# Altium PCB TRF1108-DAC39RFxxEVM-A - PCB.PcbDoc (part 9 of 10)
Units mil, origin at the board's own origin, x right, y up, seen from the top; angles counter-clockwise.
Board outline 4951.22 x 2726.56 mil, 16 copper layers (Top Layer, L2 GND1, L3 PWR1, L4 GND2, L5 PWR2, L6 GND3, L7 Ctrl Signal 1, L8 GND4, L9 GND5, L10 Ctrl Signal 2, L11 GND6, L12 PWR3, L13 GND7, L14 PWR4, L15 GND8, Bottom Layer), stack 80.2 mil thick; 705 components, 433 nets, 3633 pads, 1678 vias.
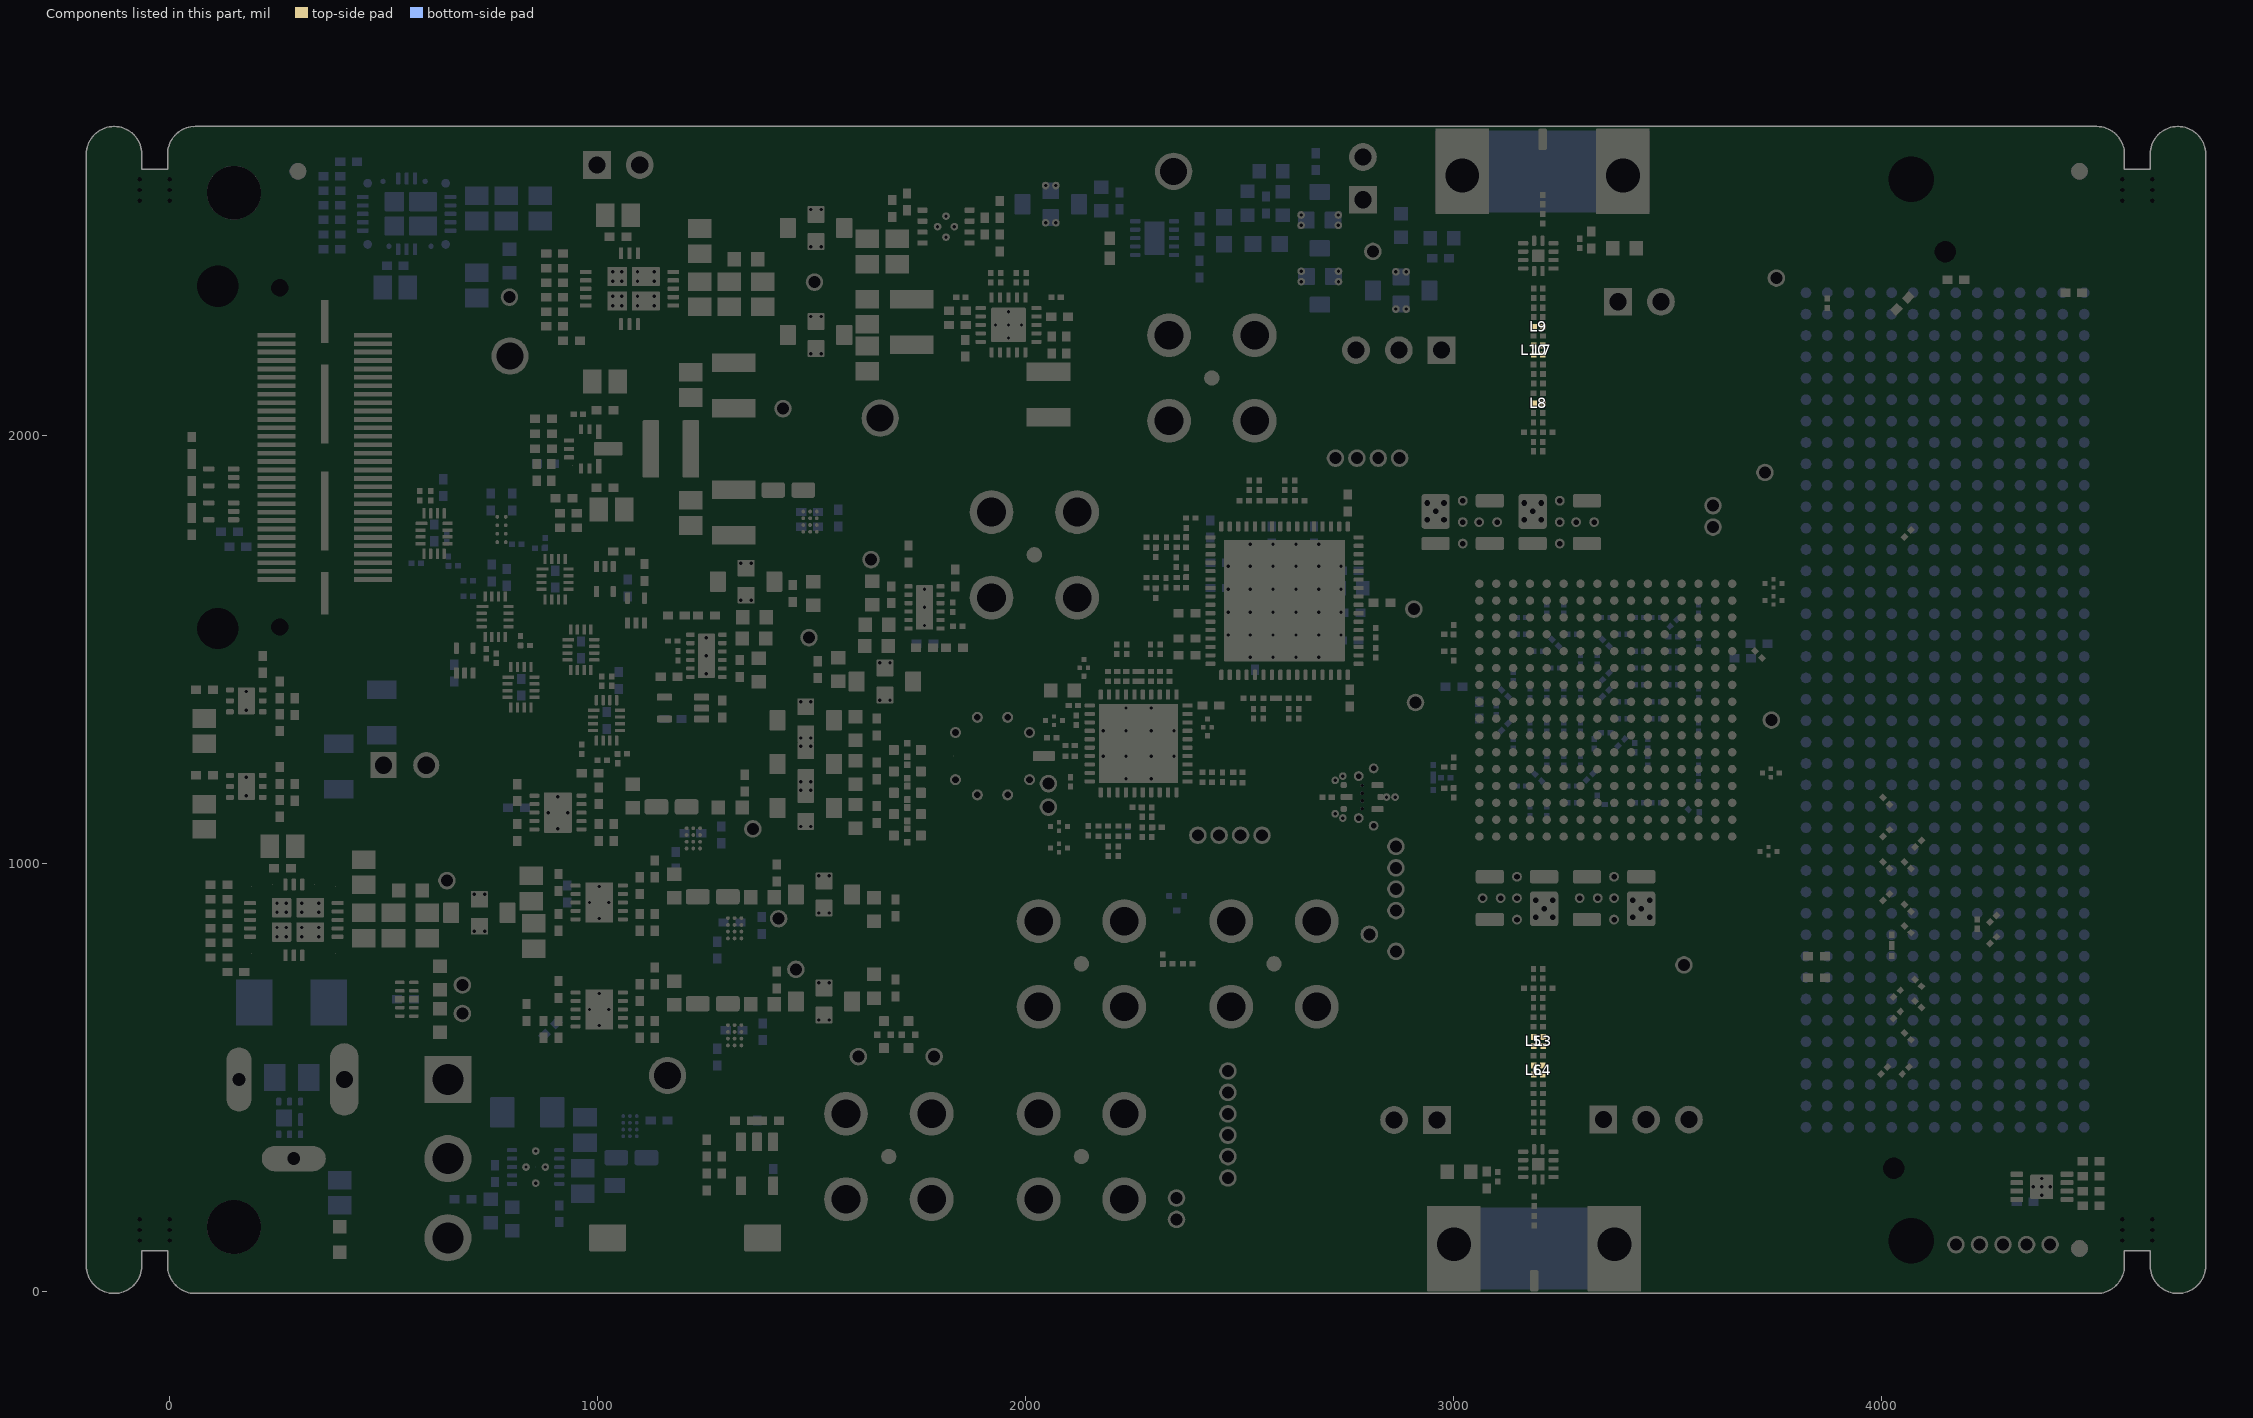
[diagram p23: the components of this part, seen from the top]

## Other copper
Top Layer:
  region net 12V: 53.27,1316.61 53.27,1359.92 140.83,1359.92 147.74,1359.92 cw(c147.74,1357.97) 149.69,1357.97 149.69,1350.06 cw(c147.74,1350.06) 147.74,1348.11 132.8,1348.11 ccw(c132.8,1338.27) 122.96,1338.27 122.96,1331.18 cw(c108.39,1331.18) 108.39,1316.61
  region net 12V: 53.27,1116.61 53.27,1159.92 140.83,1159.92 147.74,1159.92 cw(c147.74,1157.97) 149.69,1157.97 149.69,1150.06 cw(c147.74,1150.06) 147.74,1148.11 132.8,1148.11 ccw(c132.8,1138.27) 122.96,1138.27 122.96,1131.18 cw(c108.39,1131.18) 108.39,1116.61
  region net NetC108_2: 1718.11,1553.61 ccw(c1718.11,1551.64) 1716.14,1551.64 1716.14,1545.73 cw(c1695,1545.73) 1695,1524.59 1663.35,1524.59 1663.35,1491.13 1694.84,1491.13 cw(c1694.84,1467.86) 1718.11,1467.86 1718.11,1402.99 ccw(c1719.98,1402.99) 1719.98,1401.12 1753.64,1401.12 ccw(c1753.64,1402.99) 1755.51,1402.99 1755.51,1446.49 1755.51,1516.55 ccw(c1747,1516.55) 1747,1525.06 cw(c1747,1536.23) 1735.83,1536.23 1735.83,1551.64 ccw(c1733.86,1551.64) 1733.86,1553.61
  region net 3p8V_Clock_LDO: 1712.5,1612.66 cw(c1712.5,1616.01) 1709.15,1616.01 ccw(c1705.61,1616.01) 1705.61,1619.55 1676.14,1619.55 1624.25,1619.55 1624.25,1588.05 1665.14,1588.05 ccw(c1665.14,1591.01) 1668.1,1591.01 cw(c1673.02,1591.01) 1673.02,1595.93 1706.12,1595.93 ccw(c1706.12,1597.9) 1708.08,1597.9 cw(c1713.01,1597.9) 1713.01,1602.82 1733.86,1602.82 ccw(c1733.86,1604.79) 1735.83,1604.79 1735.83,1610.69 ccw(c1733.86,1610.69) 1733.86,1612.66
  region net VEExB: 1497.13,1440.49 ccw(c1493.16,1440.49) 1493.16,1444.46 1445.89,1444.46 ccw(c1445.89,1434.46) 1435.89,1434.46 1435.89,1414.46 ccw(c1445.89,1414.46) 1445.89,1404.46 1492.61,1404.46 ccw(c1492.61,1408.99) 1497.13,1408.99 1580.6,1408.99 cw(c1580.6,1403.37) 1586.22,1403.37 1586.22,1402.99 1588.09,1401.12 1621.75,1401.12 1623.62,1402.99 1623.62,1446.49 ccw(c1621.75,1446.49) 1621.75,1448.36 1588.09,1448.36 ccw(c1588.09,1446.49) 1586.22,1446.49 1586.22,1446.11 cw(c1580.6,1446.11) 1580.6,1440.49
  region net NetR90_1: 1792.91,1553.61 ccw(c1792.91,1551.64) 1790.94,1551.64 1790.94,1537.21 cw(c1780.31,1537.21) 1780.31,1526.57 ccw(c1780.31,1517.52) 1771.26,1517.52 1771.26,1493.84 1824.88,1493.84 1824.88,1515.33 ccw(c1817.64,1515.33) 1817.64,1522.57 cw(c1817.64,1529.58) 1810.63,1529.58 1810.63,1551.64 ccw(c1808.66,1551.64) 1808.66,1553.61
  region net 3p8V_Clock_LDO: 1624.25,1619.55 ccw(c1620.28,1619.55) 1620.28,1623.53 1573.01,1623.53 ccw(c1573.01,1613.53) 1563.01,1613.53 1563.01,1593.53 ccw(c1573.01,1593.53) 1573.01,1583.53 1619.72,1583.53 ccw(c1619.72,1588.05) 1624.25,1588.05 1657.72,1588.05 1657.72,1619.55
  region net VDDCSR: 1666.8,1112.95 ccw(c1667.07,1118.15) 1667.07,1112.94 cw(c1667.07,1104.67) 1675.34,1104.67 1675.34,1055.31 ccw(c1677.74,1055.31) 1677.74,1052.91 1701.32,1052.91 ccw(c1701.32,1055.28) 1703.68,1055.28 1703.68,1174.17 ccw(c1701.32,1174.17) 1701.32,1176.53 1682.42,1176.53 ccw(c1682.42,1174.17) 1680.06,1174.17 1680.06,1171.3 cw(c1661.87,1171.3) 1661.87,1153.11 1661.87,1133.43 1652.02,1133.43 1642.18,1121.61 1645.27,1121.61 cw(c1645.27,1117.13) 1649.75,1117.13 ccw(c1653.94,1117.13) 1653.94,1112.94 1666.55,1112.94 ccw(c1666.55,1117.56)
  region net VDDCSR: 1661.87,1121.61 1661.87,1153.11 1535.19,1153.11 ccw(c1535.19,1151.24) 1533.32,1151.24 1533.32,1107.74 ccw(c1535.19,1107.74) 1535.19,1105.87 1568.85,1105.87 ccw(c1568.85,1107.74) 1570.72,1107.74 cw(c1584.6,1107.74) 1584.6,1121.61
  region net VDDCLK18: 1743.05,1055.28 1743.05,1074.18 cw(c1745.41,1074.18) 1745.41,1076.54 1764.31,1076.54 cw(c1772.38,1076.54) 1772.38,1084.61 1794.86,1084.61 cw(c1794.86,1074.53) 1804.94,1074.53 1804.94,1054.79 cw(c1794.71,1054.79) 1794.71,1044.56 1772.67,1044.56 cw(c1772.67,1052.92) 1764.31,1052.92 1745.41,1052.92 cw(c1745.41,1055.28)
  region net VDDSYS18: 1743.05,1105.28 1743.05,1124.18 cw(c1745.41,1124.18) 1745.41,1126.54 1764.31,1126.54 cw(c1772.38,1126.54) 1772.38,1134.61 1794.86,1134.61 cw(c1794.86,1124.53) 1804.94,1124.53 1804.94,1104.79 cw(c1794.71,1104.79) 1794.71,1094.56 1772.67,1094.56 cw(c1772.67,1102.92) 1764.31,1102.92 1745.41,1102.92 cw(c1745.41,1105.28)
  region net VDDR: 1743.05,1155.28 1743.05,1174.18 cw(c1745.41,1174.18) 1745.41,1176.54 1764.31,1176.54 cw(c1772.38,1176.54) 1772.38,1184.61 1794.86,1184.61 cw(c1794.86,1174.53) 1804.94,1174.53 1804.94,1154.79 cw(c1794.71,1154.79) 1794.71,1144.56 1772.67,1144.56 cw(c1772.67,1152.92) 1764.31,1152.92 1745.41,1152.92 cw(c1745.41,1155.28)
  region net VDDIO: 1668.76,1326.34 ccw(c1672.73,1326.34) 1672.73,1322.36 1720,1322.36 ccw(c1720,1332.36) 1730,1332.36 1730,1352.36 ccw(c1720,1352.36) 1720,1362.36 1673.28,1362.36 ccw(c1673.28,1357.83) 1668.76,1357.83 1535.19,1357.83 ccw(c1535.19,1355.96) 1533.32,1355.96 1533.32,1312.46 ccw(c1535.19,1312.46) 1535.19,1310.59 1568.85,1310.59 ccw(c1568.85,1312.46) 1570.72,1312.46 cw(c1584.6,1312.46) 1584.6,1326.34
  region net VDDA18A: 1743.05,1205.28 1743.05,1224.18 cw(c1745.41,1224.18) 1745.41,1226.54 1764.31,1226.54 cw(c1772.38,1226.54) 1772.38,1234.61 1794.86,1234.61 cw(c1794.86,1224.53) 1804.94,1224.53 1804.94,1204.79 cw(c1794.71,1204.79) 1794.71,1194.56 1772.67,1194.56 cw(c1772.67,1202.92) 1764.31,1202.92 1745.41,1202.92 cw(c1745.41,1205.28)
  region net VDDA18B: 1743.05,1255.28 1743.05,1274.18 cw(c1745.41,1274.18) 1745.41,1276.54 1764.31,1276.54 cw(c1772.38,1276.54) 1772.38,1284.61 1794.86,1284.61 cw(c1794.86,1274.53) 1804.94,1274.53 1804.94,1254.79 cw(c1794.71,1254.79) 1794.71,1244.56 1772.67,1244.56 cw(c1772.67,1252.92) 1764.31,1252.92 1745.41,1252.92 cw(c1745.41,1255.28)
  region net VDDLA: 1716.61,579.99 1735.5,579.99 cw(c1735.5,577.63) 1737.87,577.63 1737.87,558.74 cw(c1737.87,550.67) 1745.93,550.67 1745.93,528.18 cw(c1735.86,528.18) 1735.86,518.11 1716.11,518.11 cw(c1716.11,528.33) 1705.89,528.33 1705.89,550.38 cw(c1714.24,550.38) 1714.24,558.74 1714.24,577.63 cw(c1716.61,577.63)
  region net VDDLB: 1659.41,579.99 1678.31,579.99 cw(c1678.31,577.63) 1680.67,577.63 1680.67,558.73 cw(c1680.67,550.67) 1688.74,550.67 1688.74,528.18 cw(c1678.66,528.18) 1678.66,518.11 1658.92,518.11 cw(c1658.92,528.33) 1648.69,528.33 1648.69,550.38 cw(c1657.05,550.38) 1657.05,558.73 1657.05,577.63 cw(c1659.41,577.63)
  region net VDDL: 1575.89,699.11 cw(c1577.76,699.11) 1577.76,700.98 1734.32,700.98 cw(c1734.32,697.29) 1738.01,697.29 1738.01,627.8 cw(c1729.28,627.8) 1729.28,619.37 1707,619.37 1707,619.4 cw(c1706.4,625.34) 1706.4,619.37 1662.84,619.37 cw(c1662.84,625.34) 1656.87,625.34 1656.87,637.48 ccw(c1640.61,637.48) 1640.61,653.74 1577.76,653.74 cw(c1577.76,655.61) 1575.89,655.61
  region net VDDA: 1661.87,1223.98 cw(c1661.87,1205.79) 1680.06,1205.79 1680.06,1205.28 ccw(c1682.42,1205.28) 1682.42,1202.91 1701.32,1202.91 ccw(c1701.32,1205.28) 1703.68,1205.28 1703.68,1274.17 ccw(c1701.32,1274.17) 1701.32,1276.53 1682.42,1276.53 ccw(c1682.42,1274.17) 1680.06,1274.17 1680.06,1273.66 cw(c1661.87,1273.66) 1661.87,1255.47 1535.19,1255.47 ccw(c1535.19,1253.6) 1533.32,1253.6 1533.32,1210.1 ccw(c1535.19,1210.1) 1535.19,1208.23 1568.85,1208.23 ccw(c1568.85,1210.1) 1570.72,1210.1 cw(c1584.6,1210.1) 1584.6,1223.98 1661.87,1223.98
  region net VDDCLK10: 1575.89,905.61 ccw(c1577.76,905.61) 1577.76,903.74 1734.32,903.74 ccw(c1734.32,907.43) 1738.01,907.43 1738.01,976.93 ccw(c1729.28,976.93) 1729.28,985.35 1707,985.35 1707,985.32 ccw(c1706.4,979.38) 1706.4,985.35 1662.84,985.35 ccw(c1662.84,979.38) 1656.87,979.38 1656.87,967.24 cw(c1640.61,967.24) 1640.61,950.98 1577.76,950.98 ccw(c1577.76,949.11) 1575.89,949.11
  region net NetFB4_1: 1282.3,653.74 cw(c1282.3,659.72) 1276.32,659.72 1276.32,683.98 cw(c1282.3,683.98) 1282.3,689.96 1370.57,689.96 cw(c1370.57,687.2) 1373.33,687.2 1373.33,653.74 1282.3,653.74
  region net NetFB5_1: 1282.3,903.74 cw(c1282.3,909.72) 1276.32,909.72 1276.32,933.98 cw(c1282.3,933.98) 1282.3,939.96 1370.57,939.96 cw(c1370.57,937.2) 1373.33,937.2 1373.33,903.74 1282.3,903.74
  region net NetFB3_1: 1185.8,1113.74 cw(c1185.8,1119.72) 1179.82,1119.72 1179.82,1143.98 cw(c1185.8,1143.98) 1185.8,1149.96 1229.36,1149.96 ccw(c1232.11,1149.96) 1232.11,1147.2 1297.85,1147.2 1297.85,1113.74
  region net NetC52_2: 1391.98,1105.87 1436.96,1105.87 ccw(c1436.96,1107.74) 1438.83,1107.74 1438.83,1355.96 ccw(c1436.96,1355.96) 1436.96,1357.83 1403.3,1357.83 ccw(c1403.3,1355.96) 1401.43,1355.96 1401.43,1197.49 cw(c1384.04,1197.49) 1384.04,1180.09 1373.82,1180.09 ccw(c1373.82,1161.87) 1364.1,1177.28 1352.97,1177.28 1333.29,1177.28 1333.29,1165.23 cw(c1326.95,1165.23) 1326.95,1158.9 ccw(c1326.95,1153.42) 1321.48,1153.42 1321.48,1147.6 1321.48,1111.38 1321.48,1065.09 ccw(c1328.61,1065.09) 1328.61,1057.96 1381.66,1057.96 ccw(c1381.66,1068.17) 1391.87,1068.17 1391.87,1104.64 cw(c1398.61,1104.64)
  region net GND: 946.2,1932.16 946.2,1911.1 944.43,1911.1 925.99,1892.66 ccw(c956.38,1862.27) 913.4,1862.27 913.4,1842.58 846.89,1842.58 cw(c846.89,1879.2) 821,1853.31 cw(c853.73,1886.04) 807.44,1886.04 807.44,2003.43 cw(c860.57,2005.25) 821.71,2041.54 cw(c839.56,2020.63) 841.72,2048.03 865.35,2048.03 865.35,1993.35 841.72,1993.35 ccw(c841.72,1982.89) 831.27,1982.89 831.27,1884.86 ccw(c841.11,1884.86) 841.11,1875.02 875.08,1875.02 ccw(c875.08,1882.01) 882.06,1882.01 882.06,1905.63 901.75,1905.63 916.86,1920.75 ccw(c905.45,1932.16) 921.59,1932.16 923.17,1933.74 944.62,1933.74
  pour cut-out: 2554,765 ccw(c2580,765) 2580,739 ccw(c2580,765) 2606,765 ccw(c2580,765) 2580,791 ccw(c2580,765)
  pour cut-out: 2104,765 ccw(c2130,765) 2130,739 ccw(c2130,765) 2156,765 ccw(c2130,765) 2130,791 ccw(c2130,765)
  pour cut-out: 1654,315 ccw(c1680,315) 1680,289 ccw(c1680,315) 1706,315 ccw(c1680,315) 1680,341 ccw(c1680,315)
  pour cut-out: 2104,315 ccw(c2130,315) 2130,289 ccw(c2130,315) 2156,315 ccw(c2130,315) 2130,341 ccw(c2130,315)
  pour cut-out: 1994,1720.62 ccw(c2020,1720.62) 2020,1694.62 ccw(c2020,1720.62) 2046,1720.62 ccw(c2020,1720.62) 2020,1746.62 ccw(c2020,1720.62)
  pour cut-out: 2408.73,2133.69 ccw(c2434.73,2133.69) 2434.73,2107.69 ccw(c2434.73,2133.69) 2460.73,2133.69 ccw(c2434.73,2133.69) 2434.73,2159.69 ccw(c2434.73,2133.69)
  region net NetC147_2: 2149.41,1363.65 2159.26,1363.65 ccw(c2159.26,1365.62) 2161.22,1365.62 2161.22,1371.53 ccw(c2159.26,1371.53) 2159.26,1373.5 2149.41,1373.5 cw(c2149.41,1383.34) 2139.57,1383.34 2139.57,1410.47 ccw(c2129.5,1410.47) 2129.5,1420.54 2098,1420.54 2098,1387.07 2103.13,1387.07 cw(c2103.13,1374.87) 2115.33,1374.87 2115.33,1362.28 2157.88,1362.28 ccw(c2157.88,1365.62) 2161.22,1365.62
  region net NetC44_2: 574.14,862.75 ccw(c576.11,862.75) 576.11,860.79 674.53,860.79 ccw(c674.53,862.66) 676.4,862.66 676.4,978.53 ccw(c669.58,978.53) 669.58,985.35 584.08,985.35 ccw(c584.08,975.42) 574.14,975.42 574.14,884.41
  region net NetC125_2: 1479.53,903.74 ccw(c1479.53,905.61) 1481.4,905.61 1481.4,949.11 ccw(c1479.53,949.11) 1479.53,950.98 1468.96,950.98 cw(c1468.96,959.6) 1460.34,959.6 ccw(c1452.66,959.6) 1452.66,967.28 1408.76,967.28 1408.76,955.23 cw(c1402.43,955.23) 1402.43,948.9 ccw(c1402.43,943.42) 1396.95,943.42 1396.95,847.92 ccw(c1402.63,847.92) 1402.63,842.25 1444.78,842.25 ccw(c1444.78,849.47) 1451.99,849.47 1451.99,893.03 cw(c1462.7,893.03) 1462.7,903.74
  region net 3p8V_Clock_LDO: 1393.1,1463.07 ccw(c1397.07,1463.07) 1397.07,1459.09 1444.34,1459.09 ccw(c1444.34,1469.09) 1454.34,1469.09 1454.34,1489.09 ccw(c1444.34,1489.09) 1444.34,1499.09 1397.63,1499.09 ccw(c1397.63,1494.57) 1393.1,1494.57 1359.63,1494.57 1359.63,1463.07
  region net 1p0V_DAC: 1456.3,2033.12 ccw(c1456.3,2039.28) 1462.46,2039.28 1462.46,2075.95 ccw(c1453.57,2075.95) 1453.57,2084.84 1368.93,2084.84 1266.57,2084.84 cw(c1266.57,2093.84) 1257.57,2093.84 1257.57,2099.48 ccw(c1247.21,2099.48) 1247.2,2109.84 1190.19,2109.84 1190.19,1826.54 1245.31,1826.54 ccw(c1245.31,1837) 1255.78,1837 1255.78,1840.74 cw(c1266.57,1840.74) 1266.57,1851.54 1429.5,1851.54 ccw(c1429.5,1859.67) 1437.64,1859.67 1437.64,1883.94 ccw(c1426.74,1883.94) 1426.73,1894.84 1386.33,1894.84 cw(c1393.08,1919) 1368.93,1912.24 1368.93,1987.87 1368.93,2017.23 cw(c1384.84,2017.2) 1384.84,2033.12
  region net 3p8V_Clock_LDO: 1460.88,2210.43 ccw(c1460.88,2212.3) 1462.75,2212.3 1462.75,2255.81 1462.75,2295.92 cw(c1495.44,2295.92) 1495.44,2328.61 1528.13,2328.61 ccw(c1528.13,2337.33) 1536.85,2337.33 1536.85,2369.85 ccw(c1525.99,2369.85) 1525.99,2380.71 1481.35,2380.71 cw(c1481.35,2399.31) 1462.75,2399.31 1462.75,2505.81 ccw(c1460.88,2505.81) 1460.88,2507.68 1427.22,2507.68 ccw(c1427.22,2505.81) 1425.35,2505.81 1425.35,2462.3 cw(c1390.91,2462.3) 1390.91,2427.87 1358.38,2427.87 1358.38,2337.4 1399.18,2337.4 cw(c1399.18,2311.24) 1425.35,2311.24 1425.35,2212.3 ccw(c1427.22,2212.3) 1427.22,2210.43
  region net PwrGd_Analog: 122.96,940.14 169.25,940.14 cw(c169.25,935.59) 173.8,935.59 173.8,929.68 ccw(c175.77,929.68) 175.77,927.72 208.25,927.72 ccw(c208.25,929.69) 210.22,929.69 210.22,962.17 ccw(c208.45,962.17) 208.45,963.94 202.35,963.94 202.35,964.13 127.27,964.13 ccw(c127.27,959.83) 122.96,959.83
  region net NetC41_2: 378.53,864.65 cw(c369.48,864.53) 378.53,864.62 ccw(c380.49,864.72) 380.49,862.75 550.52,862.75 550.52,953.22 512.35,953.22 cw(c512.35,964.35) 501.22,964.35 ccw(c494.55,964.35) 494.55,971.02 313.57,971.02 ccw(c313.57,962.16) 304.71,962.16 304.71,938.54 304.71,925.68 cw(c297.89,925.68) 297.89,918.86 ccw(c297.89,916.82) 295.85,916.82 295.85,875.62 ccw(c297.89,875.62) 297.89,873.58 369.48,873.58 cw(c369.48,864.53) 378.53,864.72 ccw(c380.49,864.72)
  region net NetC17_2: 1162.77,2339.3 cw(c1153.71,2339.17) 1162.77,2339.27 ccw(c1164.73,2339.37) 1164.73,2337.4 1334.76,2337.4 1334.76,2427.87 1296.59,2427.87 cw(c1296.59,2439) 1285.46,2439 ccw(c1278.79,2439) 1278.79,2445.67 1097.81,2445.67 ccw(c1097.81,2436.81) 1088.95,2436.81 1088.95,2413.19 1088.95,2400.32 cw(c1082.13,2400.32) 1082.13,2393.5 ccw(c1082.13,2391.47) 1080.09,2391.47 1080.09,2350.27 ccw(c1082.13,2350.27) 1082.13,2348.23 1153.71,2348.23 cw(c1153.71,2339.17) 1162.77,2339.37 ccw(c1164.73,2339.37)
  region net PwrGd_Clock: 907.2,2414.79 953.49,2414.79 cw(c953.49,2410.24) 958.04,2410.24 958.04,2404.33 ccw(c960.01,2404.33) 960.01,2402.36 992.49,2402.36 ccw(c992.49,2404.33) 994.46,2404.33 994.46,2436.81 ccw(c992.69,2436.81) 992.69,2438.58 986.59,2438.58 986.59,2438.78 911.51,2438.78 ccw(c911.51,2434.47) 907.2,2434.47
  region net GND: 1051.55,2411.22 cw(c1051.55,2413.19) 1049.58,2413.19 1049.58,2436.81 cw(c1051.55,2436.81) 1051.55,2438.78 ccw(c1051.55,2442.72) 1055.48,2442.72 1055.48,2541.88 1098.79,2541.88 1098.79,2486.76 cw(c1090.67,2486.76) 1090.67,2478.65 1084.59,2478.65 ccw(c1084.59,2473.17) 1079.11,2473.17 1079.11,2413.19 cw(c1077.14,2413.19) 1077.14,2411.22
  region net GND: 267.31,936.57 cw(c267.31,938.54) 265.34,938.54 265.34,962.16 cw(c267.31,962.16) 267.31,964.13 ccw(c267.31,968.07) 271.24,968.07 271.24,1067.24 314.55,1067.24 314.55,1012.12 cw(c306.43,1012.12) 306.43,1004 300.35,1004 ccw(c300.35,998.52) 294.87,998.52 294.87,938.54 cw(c292.9,938.54) 292.9,936.57
  region net GND: 162.33,736.14 267.52,736.14 ccw(c267.52,743.27) 274.64,743.27 275.19,796.81 cw(c285.6,796.81) 285.6,807.23 295.89,807.23 cw(c295.09,797.61) 304.71,796.81 304.71,743.27 ccw(c311.5,742.93) 311.17,736.14 414.43,736.35 ccw(c414.43,745.98) 424.06,745.98 424.06,801.67 cw(c426.09,801.67) 426.09,803.7 629.26,803.7 629.26,847.01 422.04,847.01 cw(c422.04,850.94) 418.1,850.94 ccw(c416.14,850.95) 416.13,852.91 373.2,852.91 cw(c373.2,856.35) 369.76,856.35 ccw(c364.34,856.35) 364.34,861.77 296.45,861.77 cw(c296.89,874.66) 284.04,873.58 284.04,916.82 ccw(c282,916.82) 282,918.86 182.66,918.86 ccw(c182.66,910) 173.8,910 173.8,904.09 ccw(c175.77,904.09) 175.77,902.12 200.1,902.12 cw(c200.11,889.1) 213.14,889.09 213.26,889.09 213.26,812.65 cw(c208.26,812.64) 208.25,807.64 191.63,807.64 ccw(c191.62,778.34) 162.33,778.34
  region net GND: 1143.45,580.51 1058.54,580.51 cw(c1058.54,592.25) 1046.8,592.25 1046.8,621.46 cw(c1049.16,621.46) 1049.16,623.82 1068.06,623.82 cw(c1068.06,621.46) 1070.42,621.46 1070.42,616.73 ccw(c1083.02,616.73) 1083.02,604.13 1143.45,604.13
  region net GND: 1143.45,830.51 1058.54,830.51 cw(c1058.54,842.25) 1046.8,842.25 1046.8,871.46 cw(c1049.16,871.46) 1049.16,873.82 1068.06,873.82 cw(c1068.06,871.46) 1070.42,871.46 1070.42,866.73 ccw(c1083.02,866.73) 1083.02,854.13 1143.45,854.13
  region net GND: 1053.48,1944.57 ccw(c1020.6,1942.99) 1019.03,1942.99 1019.03,1912.88 ccw(c1020.8,1912.88) 1020.8,1911.1 cw(c1020.8,1906.97) 1024.93,1906.97 1024.93,1866.81 ccw(c1031.74,1866.81) 1031.74,1860 1033.88,1860 cw(c1033.88,1854.09) 1039.78,1854.09 1039.78,1798.98 1083.09,1798.98 1083.09,1863.79 ccw(c1063.27,1863.79) 1063.27,1883.61 cw(c1063.27,1891.44) 1055.45,1891.44 1055.45,1942.6 ccw(c1053.48,1942.6)
  region net GND: 1053.48,1991.81 ccw(c1053.48,1993.78) 1054.87,1992.39 ccw(c1053.48,1993.78) 1055.45,1993.78 1055.45,2067.14 cw(c1099.13,2067.14) 1068.24,2098.03 1068.24,2153.15 1024.93,2153.15 1024.93,2048.7 1024.93,2035.25 cw(c1010.82,2035.25) 1020.8,2025.28 ccw(c1020.8,2023.5) 1019.03,2023.5 1019.03,1993.39 ccw(c1020.6,1993.39) 1020.6,1991.81
  region net NetC11_2: 1757.32,2187.4 cw(c1749.82,2178.57) 1761.41,2178.57 ccw(c1768.17,2178.57) 1768.17,2171.81 1933.21,2171.81 ccw(c1933.21,2183.31) 1944.71,2183.31 1944.71,2204.09 ccw(c1943.29,2204.09) 1943.29,2205.51 1916.01,2205.51 cw(c1916.01,2215) 1906.52,2215 1906.52,2221.61 ccw(c1905.1,2221.61) 1905.1,2223.03 1884.32,2223.03 ccw(c1884.32,2221.61) 1882.9,2221.61 1882.9,2209.58 cw(c1868.75,2209.58) 1868.75,2195.43 1833.31,2195.43 cw(c1833.31,2206.87) 1821.88,2206.87 ccw(c1795.28,2206.87) 1821.78,2209.08 1821.88,2209 ccw(c1796.5,2209) 1814.44,2226.95 1798.91,2242.48 ccw(c1788.76,2232.44) 1798.8,2242.6 ccw(c1764.27,2207.95) 1764.27,2256.86 1762.86,2256.86 1762.92,2256.81 ccw(c1761.41,2233.46) 1761.41,2256.86 1678.65,2256.86 cw(c1678.65,2278.07) 1657.44,2278.07 1657.44,2280.71 1582.14,2280.71 ccw(c1582.14,2255.81) 1557.24,2255.81 1557.24,2212.3 ccw(c1582.14,2212.3) 1582.14,2187.4
  region net GND: 1046.95,1040.51 962.04,1040.51 cw(c962.04,1052.25) 950.3,1052.25 950.3,1081.46 cw(c952.66,1081.46) 952.66,1083.82 971.56,1083.82 cw(c971.56,1081.46) 973.92,1081.46 973.92,1076.73 ccw(c986.52,1076.73) 986.52,1064.13 1046.95,1064.13
  region net NetR85_1: 1224.44,1529.01 ccw(c1224.44,1530.98) 1226.41,1530.98 1226.41,1545.41 cw(c1237.04,1545.41) 1237.04,1556.05 ccw(c1237.04,1565.1) 1246.09,1565.1 1246.09,1588.78 1192.47,1588.78 1192.47,1567.3 ccw(c1199.71,1567.3) 1199.71,1560.05 cw(c1199.71,1553.04) 1206.72,1553.04 1206.72,1530.98 ccw(c1208.69,1530.98) 1208.69,1529.01
  region net NetC100_2: 1299.24,1529.01 ccw(c1299.24,1530.98) 1301.21,1530.98 1301.21,1536.89 cw(c1322.35,1536.89) 1322.35,1558.03 1354,1558.03 1354,1591.49 1322.51,1591.49 cw(c1322.51,1614.76) 1299.24,1614.76 1299.24,1679.63 ccw(c1297.37,1679.63) 1297.37,1681.5 1263.71,1681.5 ccw(c1263.71,1679.63) 1261.84,1679.63 1261.84,1636.13 1261.84,1566.07 ccw(c1270.35,1566.07) 1270.35,1557.56 cw(c1270.35,1546.39) 1281.52,1546.39 1281.52,1530.98 ccw(c1283.49,1530.98) 1283.49,1529.01
  region net 3p8V_Clock_LDO: 1304.85,1469.96 cw(c1304.85,1466.61) 1308.2,1466.61 ccw(c1311.74,1466.61) 1311.74,1463.07 1341.21,1463.07 1393.1,1463.07 1393.1,1494.57 1352.21,1494.57 ccw(c1352.21,1491.61) 1349.25,1491.61 cw(c1344.33,1491.61) 1344.33,1486.69 1311.23,1486.69 ccw(c1311.23,1484.72) 1309.27,1484.72 cw(c1304.34,1484.72) 1304.34,1479.8 1283.49,1479.8 ccw(c1283.49,1477.83) 1281.52,1477.83 1281.52,1471.93 ccw(c1283.49,1471.93) 1283.49,1469.96
  region net VEExA: 1520.22,1642.13 ccw(c1524.19,1642.13) 1524.19,1638.16 1571.46,1638.16 ccw(c1571.46,1648.16) 1581.46,1648.16 1581.46,1668.16 ccw(c1571.46,1668.16) 1571.46,1678.16 1524.74,1678.16 ccw(c1524.74,1673.63) 1520.22,1673.63 1436.75,1673.63 cw(c1436.75,1679.25) 1431.13,1679.25 1431.13,1679.63 1429.26,1681.5 1395.6,1681.5 1393.73,1679.63 1393.73,1636.13 ccw(c1395.6,1636.13) 1395.6,1634.26 1429.26,1634.26 ccw(c1429.26,1636.13) 1431.13,1636.13 1431.13,1636.51 cw(c1436.75,1636.51) 1436.75,1642.13
  region net GND: 1784.8,2339.76 1784.8,2284.94 cw(c1773.99,2284.94) 1773.99,2274.12 1693.62,2274.12 cw(c1693.62,2285.3) 1682.44,2285.3 1682.44,2339.76
  region net GND: 1266.57,1745.24 1266.57,1800.06 cw(c1277.38,1800.06) 1277.38,1810.88 1357.75,1810.88 cw(c1357.75,1799.7) 1368.93,1799.7 1368.93,1745.24
  region net GND: 1368.93,2191.14 1368.93,2136.32 cw(c1358.11,2136.32) 1358.11,2125.5 1277.75,2125.5 cw(c1277.75,2136.68) 1266.57,2136.68 1266.57,2191.14
  region net NetC51_2: 980.94,1113.74 1065.37,1113.74 1147.85,1113.74 1147.85,1147.2 ccw(c1145.1,1147.2) 1145.1,1149.96 992.26,1149.96 cw(c992.26,1156.62) 985.61,1156.62 985.61,1159.59 ccw(c982.64,1159.59) 982.64,1162.56 952.66,1162.56 ccw(c952.66,1160.2) 950.3,1160.2 950.3,1116.1 ccw(c952.66,1116.1) 952.66,1113.74 980.88,1113.74 ccw(c980.88,1118.46)
  region net NetC124_2: 1077.44,903.74 1161.87,903.74 1244.35,903.74 1244.35,937.2 ccw(c1241.6,937.2) 1241.6,939.96 1088.76,939.96 cw(c1088.76,946.62) 1082.11,946.62 1082.11,949.59 ccw(c1079.14,949.59) 1079.14,952.56 1049.16,952.56 ccw(c1049.16,950.2) 1046.8,950.2 1046.8,906.1 ccw(c1049.16,906.1) 1049.16,903.74 1077.38,903.74 ccw(c1077.38,908.46)
  region net NetC116_2: 1077.44,653.74 1161.87,653.74 1244.35,653.74 1244.35,687.2 ccw(c1241.6,687.2) 1241.6,689.96 1088.76,689.96 cw(c1088.76,696.62) 1082.11,696.62 1082.11,699.59 ccw(c1079.14,699.59) 1079.14,702.56 1049.16,702.56 ccw(c1049.16,700.2) 1046.8,700.2 1046.8,656.1 ccw(c1049.16,656.1) 1049.16,653.74 1077.38,653.74 ccw(c1077.38,658.46)
  region net NetC24_2: 1762.84,2437.4 ccw(c1762.84,2444.87) 1770.3,2444.87 1770.3,2478.76 ccw(c1768.35,2478.76) 1768.35,2480.71 1638.28,2480.71 ccw(c1638.25,2477.95) 1638.25,2480.71 1627.05,2480.71 cw(c1627.05,2489.01) 1618.75,2489.01 1618.75,2480.71 1618.75,2497.31 ccw(c1608.39,2497.31) 1608.39,2507.68 1558.05,2507.68 ccw(c1558.05,2505.81) 1556.18,2505.81 1556.18,2462.3 ccw(c1558.05,2462.3) 1558.05,2460.43 1564.11,2460.43 cw(c1564.11,2451.1) 1573.45,2451.1 ccw(c1587.14,2451.1) 1587.14,2437.4
  region net GND: 2002.11,2020.04 2002.11,2074.87 cw(c2012.93,2074.87) 2012.93,2085.69 2093.29,2085.69 cw(c2093.29,2074.51) 2104.47,2074.51 2104.47,2020.04
  region net 3p3V_Utility: 329.54,1334.33 ccw(c329.54,1346.49) 341.7,1346.49 ccw(c330.23,1346.49) 330.23,1357.95 269.41,1357.95 cw(c269.41,1359.92) 267.45,1359.92 217.6,1359.92 210.69,1359.92 ccw(c210.69,1357.97) 208.74,1357.97 208.74,1350.06 ccw(c210.69,1350.06) 210.69,1348.11 229.94,1348.11 cw(c229.94,1342.81) 235.24,1342.81 ccw(c241.75,1342.81) 241.75,1336.3 280.79,1336.3 cw(c280.79,1334.33) 282.76,1334.33 302.45,1334.33
  region net 5V_Utility: 329.54,1134.33 ccw(c329.54,1146.49) 341.7,1146.49 ccw(c330.23,1146.49) 330.23,1157.95 269.41,1157.95 cw(c269.41,1159.92) 267.45,1159.92 217.6,1159.92 210.69,1159.92 ccw(c210.69,1157.97) 208.74,1157.97 208.74,1150.06 ccw(c210.69,1150.06) 210.69,1148.11 229.94,1148.11 cw(c229.94,1142.81) 235.24,1142.81 ccw(c241.75,1142.81) 241.75,1136.3 280.79,1136.3 cw(c280.79,1134.33) 282.76,1134.33 302.45,1134.33
  region net 3p3V_Clock: 1856.92,2442.91 1856.92,2480.71 1948.57,2480.71 1950.71,2480.71 ccw(c1950.71,2489) 1959,2489 cw(c1968,2489) 1968,2498 1989,2498 cw(c1989,2489) 1998,2489 1998,2448 cw(c1989,2448) 1989,2439 1968,2439 cw(c1968,2448) 1959,2448 ccw(c1949.91,2448) 1949.91,2457.09 1903.88,2457.09 ccw(c1903.88,2452.2) 1899,2452.2 1899,2452 cw(c1889.91,2452) 1889.91,2442.91 1888.59,2442.91
  region net 2p5V_Clock: 1974.63,2183.5 ccw(c1983.13,2183.5) 1983.13,2175 1996.76,2175 cw(c1996.76,2169.65) 2002.11,2169.65 2002.11,2115.19 ccw(c2013.29,2115.19) 2013.29,2104.01 2093.66,2104.01 ccw(c2093.66,2114.82) 2104.47,2114.82 2104.47,2169.65 2104.47,2203.27 2048.17,2203.27 cw(c2048.17,2215) 2036.44,2215 2036.44,2221.61 ccw(c2035.03,2221.61) 2035.03,2223.03 2014.24,2223.03 ccw(c2014.24,2221.61) 2012.82,2221.61 2012.82,2215 cw(c2003.33,2215) 2003.33,2205.51 1976.05,2205.51 ccw(c1976.05,2204.09) 1974.63,2204.09
  region net 12V: 253.53,936.57 ccw(c253.53,938.54) 255.5,938.54 255.5,962.17 255.5,1067.24 212.19,1067.24 212.19,1007.02 ccw(c219.25,1007.02) 219.25,999.96 cw(c219.25,993.24) 225.97,993.24 225.97,938.54 ccw(c227.94,938.54) 227.94,936.57
  region net 12V: 1009.19,1991.79 1009.19,2153.15 965.88,2153.15 965.88,2098.03 ccw(c976.31,2098.03) 976.31,2087.6 976.74,2087.6 cw(c976.74,2078.78) 985.56,2078.78 985.56,2042.41 ccw(c989.79,2042.41) 989.79,2038.19 cw(c989.79,2032.57) 995.41,2032.57 995.41,1991.79
  region net 12V: 980.73,1798.98 980.73,1856.73 cw(c984,1856.73) 984,1860 ccw(c984,1861.56) 985.56,1861.56 985.56,1889.35 cw(c993.02,1889.35) 993.02,1896.8 ccw(c993.02,1899.19) 995.41,1899.19 995.41,1944.59 1008.5,1944.59 1008.5,1943.9 1009.19,1943.9 1009.19,1887.68 1009.19,1867.99 ccw(c1023.08,1867.99) 1023.08,1854.09 1024.03,1854.09 1024.03,1798.98
  region net 12V: 1037.77,2411.22 ccw(c1037.77,2413.19) 1039.74,2413.19 1039.74,2436.81 1039.74,2541.88 996.43,2541.88 996.43,2481.67 ccw(c1003.49,2481.67) 1003.49,2474.61 cw(c1003.49,2467.89) 1010.21,2467.89 1010.21,2413.19 ccw(c1012.18,2413.19) 1012.18,2411.22
  region net DVDD: 1452.6,1918.1 cw(c1461.15,1918.1) 1461.15,1926.65 1524.81,1926.65 cw(c1524.81,1920.94) 1530.52,1920.94 1530.52,1857.56 cw(c1526.65,1857.56) 1526.65,1853.69 1458.57,1853.69 cw(c1458.57,1859.67) 1452.6,1859.67
  region net NetL1_1: 993.04,1952.44 1065.83,1952.44 1094.32,1923.95 1094.32,1894.38 1150.6,1894.38 1150.6,2041.99 1094.32,2041.99 1094.32,2012.43 1065.83,1983.94 993.04,1983.94
  pour cut-out: 3187.05,2715.58 3227.84,2715.58 3227.84,2442.64 3187.05,2442.64
  pour cut-out: 3229.41,778.93 3166.58,778.93 3166.58,320.18 3229.41,320.18
  pour cut-out: 3165.79,1933.06 3228.62,1933.06 3228.62,2395.4 3165.79,2395.4
  region net 5V_TRF: 3410.2,2453.28 3442.11,2453.28 3451.7,2462.87 3482.96,2462.87 3493.56,2452.27 3493.56,2420.67 3485.36,2412.47 3449.04,2412.47 3441.7,2419.81 3410.2,2419.81
  region net 5V_TRF: 2997.96,260.63 2926.9,260.63 2921.09,266.44 2921.09,294.23 2928,301.14 2995.51,301.14 3000.25,296.39 3000.25,262.93
  region net 5V_TRF1: 3067.32,291.64 3062.57,296.39 3023.87,296.39 3023.87,262.93 3062.57,262.93 3067.49,267.85 3087.18,267.85 3091.09,271.76 3131.21,271.76 3141.25,281.8 3173.98,281.8 3173.98,291.64 3104.88,291.64
  pour cut-out: 3167.37,0 3208.15,0 3208.15,272.94 3167.37,272.94
  pour cut-out: 3348.99,1767.99 3272.99,1767.99 3272.99,1726.99 3348.99,1726.99
  pour cut-out: 3348.99,1867.99 3272.99,1867.99 3272.99,1826.99 3348.99,1826.99
  pour cut-out: 3122.22,1867.99 3046.22,1867.99 3046.22,1826.99 3122.22,1826.99
  pour cut-out: 3122.22,1767.99 3046.22,1767.99 3046.22,1726.99 3122.22,1726.99
  pour cut-out: 3046.22,947.59 3122.22,947.59 3122.22,988.59 3046.22,988.59
  pour cut-out: 3046.22,847.59 3122.22,847.59 3122.22,888.59 3046.22,888.59
  pour cut-out: 3272.99,847.59 3348.99,847.59 3348.99,888.59 3272.99,888.59
  pour cut-out: 3272.99,947.59 3348.99,947.59 3348.99,988.59 3272.99,988.59
  region net 5V_TRF2: 3331.97,2423.94 3336.1,2419.81 3386.58,2419.81 3386.58,2453.28 3351.74,2453.28 3347.01,2448.54 3311.3,2448.54 3306.88,2444.12 3262.82,2444.12 3252.48,2433.78 3221.22,2433.78 3221.22,2423.94 3290.32,2423.94
  region net COMM_MUX_CTRL: 816.22,1458.54 816.22,1486.79 809.88,1486.79 809.88,1486.39 808.63,1486.39 808.63,1458.54
  region net 3p3V_Utility: 1002.93,1443.91 1002.93,1429.74 1039.1,1429.74 1039.1,1443.91
  region net GND: 780.13,1539.87 780.13,1518.22 802.11,1518.22 802.11,1539.87
  region net 3p3V_Utility: 577.78,1862.63 616.12,1862.63 616.12,1876.8 577.78,1876.8
  region net 3p3V_Utility: 1063.87,1738.28 1063.87,1718.6 1082.27,1718.6 1099.37,1701.5 1099.37,1687.04 1119.05,1687.04 1119.05,1710.66 1091.44,1738.28 1087.49,1738.28
  pour cut-out: 1088.95,2254.65 1088.96,2254.65 1088.95,2259.63 1088.95,2259.65 1088.92,2273.35 1087.77,2276.94 1085.34,2279.81 1081.99,2281.53 1080.13,2281.87 1069.84,2281.87 1067.81,2281.67 1064.05,2280.12 1061.18,2277.24 1059.62,2273.49 1059.42,2271.46 1059.42,2254.65 1059.43,2254.65 1059.45,2245.94 1060.6,2242.36 1063.03,2239.48 1066.38,2237.76 1068.24,2237.42 1078.53,2237.42 1080.56,2237.62 1084.32,2239.17 1087.19,2242.05 1088.75,2245.8 1088.95,2247.83
  pour cut-out: 304.71,780 304.72,780 304.71,784.98 304.71,785 304.68,798.7 303.53,802.29 301.1,805.16 297.75,806.89 295.89,807.23 285.6,807.23 283.57,807.03 279.81,805.47 276.94,802.6 275.39,798.84 275.19,796.81 275.18,780 275.19,780 275.21,771.3 276.36,767.71 278.8,764.83 282.14,763.11 284.01,762.77 294.29,762.77 296.32,762.97 300.08,764.53 302.95,767.4 304.51,771.16 304.71,773.19
  pour cut-out: 2360,905 2384.82,880.18 2386.21,880.18 2401.89,895.87 2399.54,898.22 2399.54,919.78
  pour cut-out: 2014.35,1237.46 2014.35,1263.46 2014.87,1263.98 2069.87,1263.98 2070.38,1263.46 2070.38,1237.46 2069.87,1236.95
  pour cut-out: 909.72,2053.03 813.44,2053.03 794.79,2034.39 794.79,1849.41 816.94,1827.27 913.83,1827.27 929.15,1842.58 929.15,1870.92 955.52,1897.29 955.52,2007.22
  region net NetR115_2: 60.98,1968.05 41.3,1968.05 41.3,1920.92 60.98,1920.92
  region net NetR112_2: 60.98,1795.18 41.3,1795.18 41.3,1842.3 60.98,1842.3
  region net NetC121_2: 1088.76,619.88 1143.45,619.88 1143.45,643.5 1088.76,643.5
  region net NetC128_2: 1088.76,869.88 1143.45,869.88 1143.45,893.5 1088.76,893.5
  region net NetC56_2: 992.26,1079.88 1046.95,1079.88 1046.95,1103.5 992.26,1103.5
  region net NetR32_1: 1894.68,2496.46 1949.37,2496.46 1949.37,2520.08 1894.68,2520.08
  region net NetR59_1: 1013.92,1165.71 1013.92,1220.39 990.3,1220.39 990.3,1165.71
  region net NetR108_1: 1088.76,955.71 1143.45,955.71 1143.45,979.33 1088.76,979.33
  region net NetR98_1: 1088.76,705.71 1143.45,705.71 1143.45,729.33 1088.76,729.33
  text ".Layer_Name" at 771.57,-1333.99 h60
L2 GND1:
  pour cut-out: 3171.6,2433.25 ccw(c3197.6,2433.25) 3197.6,2407.25 ccw(c3197.6,2433.25) 3223.6,2433.25 ccw(c3197.6,2433.25) 3197.6,2459.25 ccw(c3197.6,2433.25)
  pour cut-out: 2554,765 ccw(c2580,765) 2580,739 ccw(c2580,765) 2606,765 ccw(c2580,765) 2580,791 ccw(c2580,765)
  pour cut-out: 2104,765 ccw(c2130,765) 2130,739 ccw(c2130,765) 2156,765 ccw(c2130,765) 2130,791 ccw(c2130,765)
  pour cut-out: 1654,315 ccw(c1680,315) 1680,289 ccw(c1680,315) 1706,315 ccw(c1680,315) 1680,341 ccw(c1680,315)
  pour cut-out: 2104,315 ccw(c2130,315) 2130,289 ccw(c2130,315) 2156,315 ccw(c2130,315) 2130,341 ccw(c2130,315)
  pour cut-out: 1994,1720.62 ccw(c2020,1720.62) 2020,1694.62 ccw(c2020,1720.62) 2046,1720.62 ccw(c2020,1720.62) 2020,1746.62 ccw(c2020,1720.62)
  pour cut-out: 2408.73,2133.69 ccw(c2434.73,2133.69) 2434.73,2107.69 ccw(c2434.73,2133.69) 2460.73,2133.69 ccw(c2434.73,2133.69) 2434.73,2159.69 ccw(c2434.73,2133.69)
  pour cut-out: 3348.99,1767.99 3272.99,1767.99 3272.99,1726.99 3348.99,1726.99
  pour cut-out: 3348.99,1867.99 3272.99,1867.99 3272.99,1826.99 3348.99,1826.99
  pour cut-out: 3122.22,1867.99 3046.22,1867.99 3046.22,1826.99 3122.22,1826.99
  pour cut-out: 3122.22,1767.99 3046.22,1767.99 3046.22,1726.99 3122.22,1726.99
  pour cut-out: 3046.22,947.59 3122.22,947.59 3122.22,988.59 3046.22,988.59
  pour cut-out: 3046.22,847.59 3122.22,847.59 3122.22,888.59 3046.22,888.59
  pour cut-out: 3272.99,847.59 3348.99,847.59 3348.99,888.59 3272.99,888.59
  pour cut-out: 3272.99,947.59 3348.99,947.59 3348.99,988.59 3272.99,988.59
  text ".Layer_Name" at 771.57,-1353.98 h60
L3 PWR1:
  pour cut-out: 2554,765 ccw(c2580,765) 2580,739 ccw(c2580,765) 2606,765 ccw(c2580,765) 2580,791 ccw(c2580,765)
  pour cut-out: 2104,765 ccw(c2130,765) 2130,739 ccw(c2130,765) 2156,765 ccw(c2130,765) 2130,791 ccw(c2130,765)
  pour cut-out: 1654,315 ccw(c1680,315) 1680,289 ccw(c1680,315) 1706,315 ccw(c1680,315) 1680,341 ccw(c1680,315)
  pour cut-out: 2104,315 ccw(c2130,315) 2130,289 ccw(c2130,315) 2156,315 ccw(c2130,315) 2130,341 ccw(c2130,315)
  pour cut-out: 1994,1720.62 ccw(c2020,1720.62) 2020,1694.62 ccw(c2020,1720.62) 2046,1720.62 ccw(c2020,1720.62) 2020,1746.62 ccw(c2020,1720.62)
  pour cut-out: 2408.73,2133.69 ccw(c2434.73,2133.69) 2434.73,2107.69 ccw(c2434.73,2133.69) 2460.73,2133.69 ccw(c2434.73,2133.69) 2434.73,2159.69 ccw(c2434.73,2133.69)
  pour cut-out: 3348.99,1767.99 3272.99,1767.99 3272.99,1726.99 3348.99,1726.99
  pour cut-out: 3348.99,1867.99 3272.99,1867.99 3272.99,1826.99 3348.99,1826.99
  pour cut-out: 3122.22,1867.99 3046.22,1867.99 3046.22,1826.99 3122.22,1826.99
  pour cut-out: 3122.22,1767.99 3046.22,1767.99 3046.22,1726.99 3122.22,1726.99
  pour cut-out: 3046.22,947.59 3122.22,947.59 3122.22,988.59 3046.22,988.59
  pour cut-out: 3046.22,847.59 3122.22,847.59 3122.22,888.59 3046.22,888.59
  pour cut-out: 3272.99,847.59 3348.99,847.59 3348.99,888.59 3272.99,888.59
  pour cut-out: 3272.99,947.59 3348.99,947.59 3348.99,988.59 3272.99,988.59
  text ".Layer_Name" at 863,-1351 h60
L4 GND2:
  pour cut-out: 3348.99,1767.99 3272.99,1767.99 3272.99,1726.99 3348.99,1726.99
  pour cut-out: 3348.99,1867.99 3272.99,1867.99 3272.99,1826.99 3348.99,1826.99
  pour cut-out: 3122.22,1867.99 3046.22,1867.99 3046.22,1826.99 3122.22,1826.99
  pour cut-out: 3122.22,1767.99 3046.22,1767.99 3046.22,1726.99 3122.22,1726.99
  pour cut-out: 3046.22,947.59 3122.22,947.59 3122.22,988.59 3046.22,988.59
  pour cut-out: 3046.22,847.59 3122.22,847.59 3122.22,888.59 3046.22,888.59
  pour cut-out: 3272.99,847.59 3348.99,847.59 3348.99,888.59 3272.99,888.59
  pour cut-out: 3272.99,947.59 3348.99,947.59 3348.99,988.59 3272.99,988.59
  text ".Layer_Name" at 771.57,-1353.98 h60
L5 PWR2:
  pour cut-out: 3348.99,1767.99 3272.99,1767.99 3272.99,1726.99 3348.99,1726.99
  pour cut-out: 3348.99,1867.99 3272.99,1867.99 3272.99,1826.99 3348.99,1826.99
  pour cut-out: 3122.22,1867.99 3046.22,1867.99 3046.22,1826.99 3122.22,1826.99
  pour cut-out: 3122.22,1767.99 3046.22,1767.99 3046.22,1726.99 3122.22,1726.99
  pour cut-out: 3046.22,947.59 3122.22,947.59 3122.22,988.59 3046.22,988.59
  pour cut-out: 3046.22,847.59 3122.22,847.59 3122.22,888.59 3046.22,888.59
  pour cut-out: 3272.99,847.59 3348.99,847.59 3348.99,888.59 3272.99,888.59
  pour cut-out: 3272.99,947.59 3348.99,947.59 3348.99,988.59 3272.99,988.59
  text ".Layer_Name" at 787.68,-1351.68 h60
L6 GND3:
  text ".Layer_Name" at 771.57,-1353.98 h60
L11 GND6:
  text ".Layer_Name" at 771.57,-1353.98 h60
L12 PWR3:
  text ".Layer_Name" at 656.61,-1353.98 h60
L13 GND7:
  text ".Layer_Name" at 771.57,-1353.98 h60
L14 PWR4:
  text ".Layer_Name" at 656.61,-1353.98 h60
L15 GND8:
  text ".Layer_Name" at 771.57,-1353.98 h60
L7 Ctrl Signal 1:
  pour cut-out: 1109.21,1716.81 1109.21,1682.25 1115.36,1676.1 1481.8,1676.1 1753.94,1948.24 1648.13,1948.24 1416.71,1716.81
  text ".Layer_Name" at 586,-1345.49 h60
L10 Ctrl Signal 2:
  pour cut-out: 3805,1355 3805,1320.8 3939.97,1320.8 3939.97,1355.08
  pour cut-out: 705,1420 750.71,1420 799.6,1371.12 854.14,1371.12 989.79,1235.47 982.36,1228.04 778,1228.04 778,1232.09 676.95,1333.14
  pour cut-out: 987.82,1298.53 1088.43,1197.92 1088.43,1147.36 1433.95,1147.36 1450.96,1164.38 1450.96,1306.15
  text ".Layer_Name" at 586,-1325.49 h60
L8 GND4:
  text ".Layer_Name" at 771.57,-1333.99 h60
L9 GND5:
  text ".Layer_Name" at 771.57,-1353.98 h60
Bottom Layer:
  region net NetC176_2: 810.54,2420.12 810.54,2450.05 839.4,2478.91 892.85,2478.91 892.85,2522.22 644.09,2522.22 ccw(c644.09,2520.26) 642.13,2520.35 cw(c642.08,2520.34) 642.12,2520.33 ccw(c643.82,2520.26) 642.12,2520.26 cw(c633.07,2520.45) 633.07,2511.39 561.49,2511.39 ccw(c561.49,2509.36) 559.45,2509.36 559.45,2468.16 ccw(c561.49,2468.15) 561.49,2466.12 cw(c561.49,2459.3) 568.31,2459.3 568.31,2446.43 568.31,2420.24
  region net 12V: 517.12,2448.4 cw(c517.12,2446.43) 519.09,2446.43 519.09,2422.81 519.09,2317.74 475.79,2317.74 475.79,2377.95 cw(c482.85,2377.95) 482.85,2385.02 ccw(c482.85,2391.73) 489.57,2391.73 489.57,2446.43 cw(c491.53,2446.43) 491.53,2448.4
  region net GND: 530.91,2448.4 ccw(c530.91,2446.43) 528.94,2446.43 528.94,2422.81 ccw(c530.91,2422.81) 530.91,2420.84 cw(c530.91,2416.91) 534.84,2416.91 534.84,2317.74 578.15,2317.74 578.15,2372.86 ccw(c570.03,2372.86) 570.03,2380.98 563.95,2380.98 cw(c563.95,2386.46) 558.46,2386.46 558.46,2446.43 ccw(c556.5,2446.43) 556.5,2448.4
  region net GND: 425.93,2648.83 531.11,2648.83 cw(c531.11,2641.71) 538.24,2641.71 538.78,2588.17 ccw(c549.2,2588.17) 549.2,2577.75 559.48,2577.75 ccw(c558.69,2587.37) 568.31,2588.17 568.31,2641.71 cw(c575.1,2642.04) 574.77,2648.83 678.03,2648.62 cw(c678.03,2638.99) 687.66,2638.99 687.66,2583.31 ccw(c689.68,2583.31) 689.68,2581.28 892.85,2581.28 892.85,2537.97 685.64,2537.97 ccw(c685.64,2534.03) 681.7,2534.03 cw(c679.73,2534.03) 679.73,2532.06 636.8,2532.06 ccw(c636.8,2528.62) 633.36,2528.62 cw(c627.94,2528.62) 627.94,2523.2 560.05,2523.2 ccw(c560.49,2510.32) 547.64,2511.39 547.64,2468.16 cw(c545.6,2468.16) 545.6,2466.12 446.26,2466.12 cw(c446.26,2474.97) 437.4,2474.98 437.4,2480.88 cw(c439.37,2480.88) 439.37,2482.85 463.7,2482.85 ccw(c463.7,2495.88) 476.73,2495.88 476.86,2495.88 476.86,2572.33 ccw(c471.85,2572.33) 471.85,2577.34 454.9,2577.34 cw(c454.89,2606.31) 425.93,2606.31
  region net PwrGd_TRF_LDO: 386.56,2444.83 432.85,2444.83 ccw(c432.85,2449.38) 437.4,2449.38 437.4,2455.29 cw(c439.37,2455.29) 439.37,2457.26 471.85,2457.26 cw(c471.85,2455.29) 473.82,2455.29 473.82,2422.81 cw(c472.05,2422.81) 472.05,2421.04 465.94,2421.04 465.94,2420.84 390.86,2420.84 cw(c390.86,2425.15) 386.56,2425.15
  region net NetC1_1: 705.12,446.65 cw(c742.07,446.65) 742.07,483.6 1099.53,483.6 cw(c1099.53,473.49) 1109.63,473.49 ccw(c1132.37,473.49) 1132.37,450.75 1170.18,450.75 ccw(c1170.18,497.21) 1216.63,497.21 1216.63,511.3 ccw(c1177.77,511.3) 1177.77,550.16 609.07,550.16 609.1,549.51 486.03,549.51 cw(c486.03,621.04) 414.5,621.04 414.5,729.04 329.5,729.04 ccw(c329.5,699.54) 300,699.54 300,480.53 300,436.52 ccw(c301.95,436.52) 301.95,434.57 341.78,434.57 cw(c341.78,420.2) 356.15,420.2 ccw(c365.96,420.2) 365.96,410.39 673.39,410.39 ccw(c673.39,442.13) 705.12,442.13
  region net NetC2_2: 898.42,360.03 898.43,287.58 ccw(c900.41,287.58) 900.41,285.59 931.92,285.59 cw(c931.92,279.83) 937.68,279.83 937.68,265.85 992.8,265.85 cw(c992.8,242.42) 1016.22,242.42 1016.22,229.21 1064.25,229.21 ccw(c1064.25,232.95) 1067.99,232.95 1067.99,324.36 ccw(c1062.02,324.36) 1062.02,330.33 1018.46,330.33 cw(c1018.46,340.99) 1007.8,341 1007.8,370.35 939.65,370.35 cw(c939.65,387.95) 922.05,387.95 922.05,451.68 ccw(c920.05,451.68) 920.05,453.68 866.96,453.68 ccw(c866.96,451.68) 864.96,451.68 864.96,379.52 ccw(c874.14,379.52) 874.14,370.35 888.09,370.35 cw(c888.09,360.01) 898.42,360.01 cw(c899.28,360.01)
  region net NetC130_1: 2945.7,1214.48 2945.7,1186.13 2958.3,1186.13 2958.3,1189.01 cw(c2963.3,1189.01) 2963.3,1194.01 2977.47,1194.01 2977.47,1206.61 2963.3,1206.61 cw(c2963.3,1211.61) 2958.3,1211.61 2958.3,1214.48
  region net GND: 301.95,357.8 321.94,357.8 ccw(c321.94,365.36) 329.5,365.36 329.5,402.58 ccw(c316.01,402.58) 316.01,416.06 300.57,416.06 300.57,415.49 300,415.49 300,359.74 ccw(c301.95,359.74)
  region net 12V: 529.85,1427.16 529.85,1371.55 cw(c515.4,1371.55) 515.4,1357.1 473.65,1357.1 cw(c473.65,1369.8) 460.95,1369.8 460.95,1427.16
  region net NetF1_2: 550,271.22 ccw(c575,271.22) 575,246.22 713.58,246.22 ccw(c713.58,265.91) 733.27,265.91 cw(c750.01,265.91) 750.01,282.65 807.71,282.65 ccw(c807.29,287.16) 811.81,287.58 811.81,332.43 ccw(c809.83,332.43) 809.83,334.41 cw(c809.83,338.33) 805.91,338.33 805.91,451.68 ccw(c803.91,451.68) 803.91,453.68 750.82,453.68 ccw(c750.82,451.68) 748.82,451.68 748.82,408.99 cw(c715.79,408.99) 715.79,375.97 715.6,375.57 ccw(c711.46,354.15) 711.46,375.97 576.99,375.97 ccw(c576.99,348.97) 550,348.97
  region net 5V_Utility: 429.85,1194.57 360.95,1194.57 cw(c339.3,1194.57) 339.3,1172.91 298.02,1172.91 ccw(c298.02,1157.66) 282.76,1157.66 282.76,1143.6 ccw(c292.03,1143.6) 292.03,1134.33 412.92,1134.33 ccw(c412.92,1151.26) 429.85,1151.26
  region net 12V: 1163.2,225.01 ccw(c1163.2,230.99) 1169.17,230.99 1169.17,324.51 ccw(c1163.2,324.51) 1163.2,330.49 1088.93,330.49 ccw(c1088.93,324.51) 1082.95,324.51 1082.95,230.99 ccw(c1088.93,230.99) 1088.93,225.01
  region net NetJ3_1: 360.95,1257.56 416.91,1257.56 cw(c416.91,1205.64) 468.82,1205.64 468.82,1198.7 529.85,1198.7 529.85,1320 360.95,1320
  region net NetC6_2: 783.27,180.47 816.73,180.47 816.73,223.27 ccw(c815,223.27) 815,225 cw(c815,228.19) 811.81,228.19 811.81,253.69 ccw(c809.83,253.69) 809.83,255.67 790.17,255.67 ccw(c790.17,253.69) 788.19,253.69 788.19,226.93 cw(c786.22,226.93) 786.22,224.96 ccw(c786.22,222.01) 783.27,222.01 783.27,211.97
  region net NetC5_2: 811.81,267.89 cw(c809.83,267.89) 809.83,265.91 780.66,265.91 ccw(c780.66,255.09) 769.84,255.09 769.84,243.28 ccw(c769.84,240.17) 766.73,240.17 766.73,199.25 726.43,199.25 cw(c726.43,200.95) 724.73,200.95 ccw(c720.52,200.95) 720.52,205.16 693.31,205.16 693.31,224.84 721.13,224.84 ccw(c721.13,228.45) 724.73,228.45 cw(c727.04,228.45) 727.04,230.75 737.63,230.75 ccw(c737.63,243.28) 750.16,243.28 750.16,266.9 cw(c758.61,266.9) 758.61,275.35 809.83,275.35 cw(c809.83,273.37) 811.81,273.37
  region net NetC1_2: 132.47,706.02 cw(c155.48,706.02) 155.48,729.04 240.48,729.04 cw(c240.48,699.52) 270,699.52 270,462.6 ccw(c280.32,462.6) 280.32,452.28 284.27,452.28 cw(c284.27,450.33) 286.22,450.33 286.22,359.74 cw(c284.27,359.74) 284.27,357.8 152.65,357.8 cw(c152.65,377.97) 132.47,377.97
  region net 3p3V_Utility: 2387.64,2343.17 2409.27,2343.17 2415.79,2349.69 2415.79,2380.17 2412.96,2383 2336.2,2383 2325.61,2372.41 2325.61,2351.27 2333.71,2343.17
  region net NetC264_1: 2860.04,2446.8 2924,2446.8 2924,2345.28 2961.3,2345.28 2961.3,2478.29 2860.04,2478.29
  region net 5V_TRF_EXT: 2755.04,2582.61 2843.41,2582.61 2893.5,2532.52 2893.5,2501.91 2860.1,2501.91 2844.36,2517.65 2755.04,2517.65
  region net 5p5V_TRF_DCDC: 370.81,2512.83 316.6,2512.83 316.6,2493.15 370.81,2493.15
  region net 5p5V_TRF_DCDC: 2011.53,2518.14 2011.53,2624.32 2009.59,2626.26 1979.18,2626.26 1974.13,2621.2 1974.13,2517.36 1975.22,2516.27 2009.66,2516.27
  region net 5p5V_TRF_DCDC: 2708.82,2323.71 2602.64,2323.71 2600.7,2321.77 2600.7,2291.36 2605.76,2286.31 2709.6,2286.31 2710.69,2287.4 2710.69,2321.84
  region net GND: 2200.83,2555.64 2192.96,2563.51 2159.49,2563.51 2159.49,2631.48 2175.31,2647.29 2225.93,2647.29 2233.03,2640.19 2233.03,2559.84 2228.83,2555.64
  region net GND: 2573.84,2465.6 2573.84,2381.62 2577.76,2377.7 2610.29,2377.7 2613.21,2380.62 2613.21,2465.6 2593.53,2465.6
  region net GND: 2714.25,2626.38 2714.25,2606.69 2787.76,2606.69 2787.76,2626.38
  region net GND: 2551.49,2545.89 2543.53,2553.86 2453.86,2553.86 2444.47,2563.24 2444.47,2621.86 2458.86,2636.25 2558.35,2636.25 2571.18,2623.42 2571.18,2545.89
  region net 5V_TRF: 2820.88,2458.2 2833.81,2445.27 2833.81,2248.74 2786.57,2248.74 2786.57,2407.13 2777.76,2415.94 2663.07,2415.94 2663.07,2458.2 2769.14,2458.2
  region net NetC186_1: 2710.31,2587.89 2698.5,2599.7 2698.5,2626.38 2691.61,2633.27 2583.97,2633.27 2583.97,2553.7 2588.11,2549.57 2710.31,2549.57
  region net PG_TRF: 2336.48,2426.13 2389.52,2426.13 2396.11,2419.54 2415.79,2419.54 2415.79,2395.92 2346.32,2395.92 2334.51,2407.73 2334.51,2424.16
  region net NetC183_1: 2334.51,2465.5 2362.3,2465.5 2370.75,2473.95 2436.61,2473.95 2444.47,2466.09 2550.22,2466.09 2550.22,2427.22 2432.99,2427.22 2417.76,2442.45 2371.34,2442.45 2358.13,2455.65 2334.51,2455.65
  region net NetC183_2: 2336.48,2475.34 2359.71,2475.34 2374.07,2489.69 2617.44,2489.69 2617.44,2530.58 2481.37,2530.58 2339.5,2530.58 2334.51,2525.58 2334.51,2476.49 2335.09,2475.92
  pour cut-out: 568.31,2604.98 568.32,2604.98 568.31,2600 568.31,2599.98 568.28,2586.27 567.13,2582.69 564.69,2579.81 561.35,2578.09 559.48,2577.75 549.2,2577.75 547.17,2577.95 543.41,2579.51 540.54,2582.38 538.98,2586.13 538.78,2588.17 538.78,2604.98 538.79,2604.98 538.81,2613.68 539.96,2617.27 542.39,2620.14 545.74,2621.86 547.6,2622.2 557.89,2622.2 559.92,2622 563.68,2620.45 566.55,2617.57 568.1,2613.82 568.3,2611.79
  region net 5p5V_TRF_DCDC: 814.64,2244.29 779.29,2244.29 763.49,2260.09 763.49,2347.16 752.57,2358.08 689.68,2358.08 689.68,2401.39 829.16,2401.39 829.16,2258.81
  pour cut-out: 3779.53,2053.18 3779.53,1703.67 3789.28,1713.42 3806.06,1713.42 3806.06,2041.9 3794.78,2053.18
  pour cut-out: 3399.33,1717.19 3408.44,1726.3 3507.69,1726.3 3507.69,1668.12 3501.29,1661.71 3490.82,1672.18 3399.33,1672.18
  pour cut-out: 3798.78,462.93 3801.28,465.43 3801.28,913.07 3662.28,913.07 3655.87,919.47 3604.69,868.29 3604.69,791.69 3716.37,680.01 3716.37,482.88 3748.82,482.88 3778.52,453.18
  pour cut-out: 3805,2250 3790,2235 3735,2235 3735,2085 3725,2075 3800,2075
  region net NetR45_1: 3705,1468.88 3685.31,1468.88 3685.31,1521.12 3705,1521.12
  text ".Layer_Name" at 670.45,-1351 h60
Multi-Layer:
  pour cut-out: 4306.87,1382.99 ccw(c4322.87,1382.99) 4322.87,1366.99 ccw(c4322.87,1382.99) 4338.87,1382.99 ccw(c4322.87,1382.99) 4322.87,1398.99 ccw(c4322.87,1382.99)
  pour cut-out: 4306.87,1332.99 ccw(c4322.87,1332.99) 4322.87,1316.99 ccw(c4322.87,1332.99) 4338.87,1332.99 ccw(c4322.87,1332.99) 4322.87,1348.99 ccw(c4322.87,1332.99)
  pour cut-out: 4056.87,1932.99 ccw(c4072.87,1932.99) 4072.87,1916.99 ccw(c4072.87,1932.99) 4088.87,1932.99 ccw(c4072.87,1932.99) 4072.87,1948.99 ccw(c4072.87,1932.99)
  pour cut-out: 4056.87,1882.99 ccw(c4072.87,1882.99) 4072.87,1866.99 ccw(c4072.87,1882.99) 4088.87,1882.99 ccw(c4072.87,1882.99) 4072.87,1898.99 ccw(c4072.87,1882.99)
  pour cut-out: 4056.87,2082.99 ccw(c4072.87,2082.99) 4072.87,2066.99 ccw(c4072.87,2082.99) 4088.87,2082.99 ccw(c4072.87,2082.99) 4072.87,2098.99 ccw(c4072.87,2082.99)
  pour cut-out: 4056.87,2032.99 ccw(c4072.87,2032.99) 4072.87,2016.99 ccw(c4072.87,2032.99) 4088.87,2032.99 ccw(c4072.87,2032.99) 4072.87,2048.99 ccw(c4072.87,2032.99)
  pour cut-out: 4206.87,2182.99 ccw(c4222.87,2182.99) 4222.87,2166.99 ccw(c4222.87,2182.99) 4238.87,2182.99 ccw(c4222.87,2182.99) 4222.87,2198.99 ccw(c4222.87,2182.99)
  pour cut-out: 4206.87,2132.99 ccw(c4222.87,2132.99) 4222.87,2116.99 ccw(c4222.87,2132.99) 4238.87,2132.99 ccw(c4222.87,2132.99) 4222.87,2148.99 ccw(c4222.87,2132.99)
  pour cut-out: 4456.87,882.99 ccw(c4472.87,882.99) 4472.87,866.99 ccw(c4472.87,882.99) 4488.87,882.99 ccw(c4472.87,882.99) 4472.87,898.99 ccw(c4472.87,882.99)
  pour cut-out: 4456.87,832.99 ccw(c4472.87,832.99) 4472.87,816.99 ccw(c4472.87,832.99) 4488.87,832.99 ccw(c4472.87,832.99) 4472.87,848.99 ccw(c4472.87,832.99)
  pour cut-out: 4406.87,982.99 ccw(c4422.87,982.99) 4422.87,966.99 ccw(c4422.87,982.99) 4438.87,982.99 ccw(c4422.87,982.99) 4422.87,998.99 ccw(c4422.87,982.99)
  pour cut-out: 4406.87,932.99 ccw(c4422.87,932.99) 4422.87,916.99 ccw(c4422.87,932.99) 4438.87,932.99 ccw(c4422.87,932.99) 4422.87,948.99 ccw(c4422.87,932.99)
  pour cut-out: 4456.87,1082.99 ccw(c4472.87,1082.99) 4472.87,1066.99 ccw(c4472.87,1082.99) 4488.87,1082.99 ccw(c4472.87,1082.99) 4472.87,1098.99 ccw(c4472.87,1082.99)
  pour cut-out: 4456.87,1032.99 ccw(c4472.87,1032.99) 4472.87,1016.99 ccw(c4472.87,1032.99) 4488.87,1032.99 ccw(c4472.87,1032.99) 4472.87,1048.99 ccw(c4472.87,1032.99)
  pour cut-out: 4406.87,1182.99 ccw(c4422.87,1182.99) 4422.87,1166.99 ccw(c4422.87,1182.99) 4438.87,1182.99 ccw(c4422.87,1182.99) 4422.87,1198.99 ccw(c4422.87,1182.99)
  pour cut-out: 4406.87,1132.99 ccw(c4422.87,1132.99) 4422.87,1116.99 ccw(c4422.87,1132.99) 4438.87,1132.99 ccw(c4422.87,1132.99) 4422.87,1148.99 ccw(c4422.87,1132.99)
